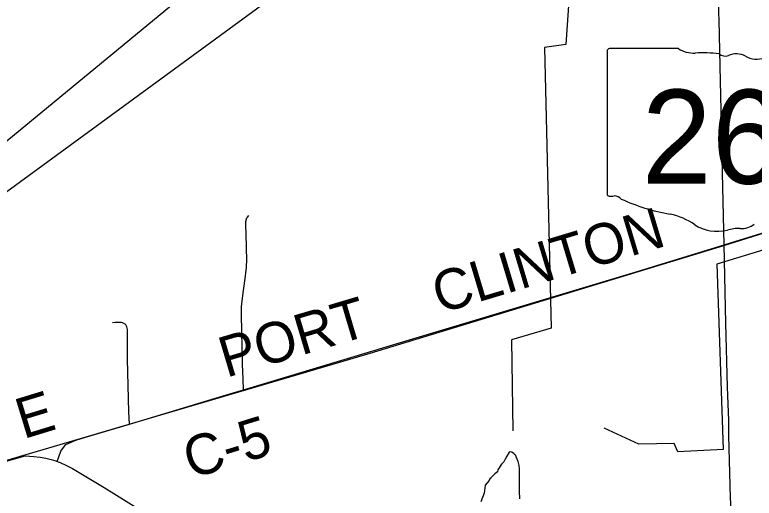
# Model space of a CAD drawing. Extents: x 0 to 34, y 0 to 22.
# Drawn here: x 6.003 to 6.521, y 18.17 to 18.509 of the extents above; entities that cross this region are included whole.
import ezdxf

# ---------------------------------------------------------------- set-up
doc = ezdxf.new("R2010")
doc.units = 0
for name, color, linetype in [('GM_X_County_Road', 7, 'Continuous'), ('GM_X_County_Road_Text', 7, 'Continuous'), ('GM_X_Minor_River', 7, 'Continuous'), ('GM_X_Rail_Line', 7, 'Continuous'), ('GM_X_State_Location', 7, 'Continuous'), ('GM_X_State_Route', 7, 'Continuous'), ('GM_X_State_Shield', 7, 'Continuous'), ('GM_X_Township_Road', 7, 'Continuous'), ('SH_Text', 7, 'Continuous')]:
    doc.layers.add(name, color=color, linetype=linetype)

msp = doc.modelspace()

# ---------------------------------------------------------------- linework, layer by layer
at = {"layer": 'GM_X_County_Road'}
msp.add_line((6.03864, 18.20727), (6.04563, 18.21028), dxfattribs=at)
for points in [[(6.4999, 18.34733), (6.50494, 18.34889), (6.53465, 18.35812), (6.66398, 18.39789), (6.6654, 18.39833)], [(6.16307, 18.2457), (6.26526, 18.27641), (6.43806, 18.32827), (6.4999, 18.34733)], [(6.08314, 18.22155), (6.11338, 18.23059), (6.15355, 18.24284), (6.16307, 18.2457)], [(6.04563, 18.21028), (6.05228, 18.21233), (6.08314, 18.22155)], [(6.0324, 18.19545), (6.03351, 18.19853), (6.03509, 18.2026), (6.03693, 18.2051), (6.03864, 18.20727)], [(5.93303, 18.17779), (5.93554, 18.17821), (5.93858, 18.1788), (5.94485, 18.18026), (5.95124, 18.18197), (5.96361, 18.18543), (5.99181, 18.19414), (6.00506, 18.19796), (6.01002, 18.19933)], [(6.01002, 18.19933), (6.01601, 18.19883), (6.02062, 18.1983), (6.02457, 18.19765), (6.02816, 18.19683), (6.03141, 18.19584), (6.0324, 18.19545), (6.03458, 18.19461), (6.03895, 18.19265), (6.04331, 18.19044)], [(6.04331, 18.19044), (6.04677, 18.18829), (6.06539, 18.17703), (6.2078, 18.08859), (6.26845, 18.05089), (6.29749, 18.0328)]]:
    msp.add_lwpolyline(points, dxfattribs=at)
at = {"layer": 'GM_X_Minor_River'}
for points in [[(6.39114, 18.52221), (6.38884, 18.4878), (6.37386, 18.48564), (6.37865, 18.28897), (6.35079, 18.28066), (6.35168, 18.21681)], [(6.97961, 18.48166), (6.49479, 18.33379), (6.49906, 18.20382), (6.46737, 18.20215), (6.46468, 18.20803), (6.44, 18.20753), (6.41565, 18.21882)], [(6.35656, 18.16909), (6.35645, 18.1746), (6.35635, 18.18087), (6.35642, 18.18581), (6.3563, 18.19018), (6.35614, 18.19246), (6.35543, 18.19532), (6.35415, 18.19875), (6.35378, 18.19971), (6.35284, 18.20029), (6.35266, 18.20086), (6.35097, 18.20183), (6.34965, 18.20204), (6.34908, 18.20186), (6.34752, 18.19904), (6.34635, 18.19696), (6.34557, 18.19564), (6.34537, 18.19508), (6.34383, 18.19358), (6.34131, 18.18963), (6.34091, 18.18811), (6.33918, 18.18662), (6.33668, 18.18438), (6.33649, 18.18381), (6.33553, 18.18325), (6.33513, 18.18212), (6.33243, 18.17874), (6.33159, 18.17325), (6.32942, 18.1672)]]:
    msp.add_lwpolyline(points, dxfattribs=at)
at = {"layer": 'GM_X_Rail_Line'}
msp.add_lwpolyline([(4.40206, 18.19809), (4.68917, 18.19409), (5.00635, 18.18976), (5.15875, 18.1876), (5.36248, 18.18265), (5.7183, 18.17956), (5.93191, 18.17708), (6.25187, 18.2714), (6.49949, 18.34686), (7.04327, 18.51787), (7.07913, 18.52777), (7.1289, 18.52993), (7.24173, 18.53643), (7.28965, 18.56333), (7.33819, 18.59766)], dxfattribs=at)
at = {"layer": 'GM_X_State_Route'}
for points in [[(6.4999, 18.34733), (6.4983, 18.4182), (6.49782, 18.44148), (6.49709, 18.47253), (6.4963, 18.50512), (6.4962, 18.50974), (6.49592, 18.5222), (6.49285, 18.64016), (6.4924, 18.65568), (6.49195, 18.67513), (6.49092, 18.71933), (6.48978, 18.75808), (6.48902, 18.78272), (6.48838, 18.8108), (6.48776, 18.84505), (6.48647, 18.88829), (6.48542, 18.93662), (6.48511, 18.95681), (6.48493, 18.96654), (6.48491, 18.98139)], [(6.5039, 18.18736), (6.5032, 18.21333), (6.503, 18.22418), (6.50208, 18.24745), (6.50093, 18.29243), (6.4999, 18.34733)], [(6.50646, 18.13067), (6.50637, 18.13629), (6.50621, 18.14474), (6.50599, 18.14914), (6.5058, 18.15195), (6.50564, 18.15363), (6.50542, 18.15546), (6.50478, 18.16187), (6.50436, 18.16989), (6.5039, 18.18736)]]:
    msp.add_lwpolyline(points, dxfattribs=at)
at = {"layer": 'GM_X_State_Shield'}
for p, q in [((6.41784, 18.48316), (6.41784, 18.3831)), ((6.46772, 18.48489), (6.41946, 18.48489))]:
    msp.add_line(p, q, dxfattribs=at)
for centre, major_axis, start_param, end_param in [((6.41973, 18.48338), (0.00191, 0), 1.712693, 3.28349), ((6.47922, 18.4965), (0.01852, 0), 4.042523, 4.731795), ((6.48536, 18.42871), (0.06648, 0), 1.404758, 1.657858), ((6.50829, 18.47233), (0.01111, 0), 0.950623, 2.079405), ((6.50045, 18.4839), (0.00534, 0), 3.836095, 5.185415), ((6.52262, 18.48819), (0.01336, 0), 4.081561, 5.145723), ((6.41974, 18.38289), (0.00193, 0), 3.00124, 4.508301), ((6.42004, 18.39312), (0.0147, 0), 4.665946, 4.897461), ((6.42304, 18.37733), (0.0053, 0), 0.519207, 1.627899), ((6.48996, 18.46723), (0.1262, 0), 4.195997, 4.488961), ((6.45233, 18.33815), (0.03949, 0), 0.823519, 1.323587), ((6.49504, 18.37683), (0.02506, 0), 4.026481, 4.996735), ((6.50952, 18.34224), (0.02059, 0), 1.495662, 1.94098), ((6.51135, 18.36934), (0.01335, 0), 4.691044, 5.507374)]:
    msp.add_ellipse(centre, major_axis=major_axis, ratio=0.8, start_param=start_param, end_param=end_param, dxfattribs=at)
at = {"layer": 'GM_X_Township_Road'}
for points in [[(6.16307, 18.2457), (6.16273, 18.25322), (6.16242, 18.26355), (6.16159, 18.29814), (6.16164, 18.30108), (6.16172, 18.30381), (6.16185, 18.30594), (6.16274, 18.31368), (6.16445, 18.32533), (6.16476, 18.32757), (6.16506, 18.33106), (6.16523, 18.33331), (6.16526, 18.33535), (6.16513, 18.34627), (6.16466, 18.36185), (6.16471, 18.36299), (6.16471, 18.36373), (6.1648, 18.36433), (6.16493, 18.36494), (6.16519, 18.36559), (6.16545, 18.36616), (6.16584, 18.36676), (6.16679, 18.36794)], [(6.08314, 18.22155), (6.08266, 18.23009), (6.08182, 18.26722), (6.08169, 18.28569), (6.08168, 18.28685), (6.08163, 18.28792), (6.08149, 18.28888), (6.08125, 18.28977), (6.08102, 18.29026), (6.08078, 18.29069), (6.08047, 18.2911), (6.08006, 18.29157), (6.07966, 18.29188), (6.07923, 18.2922), (6.07881, 18.29243), (6.07836, 18.2926), (6.07764, 18.29279), (6.07723, 18.29283), (6.0766, 18.29289), (6.07567, 18.29292), (6.0746, 18.29293), (6.07317, 18.29282), (6.07116, 18.29267)]]:
    msp.add_lwpolyline(points, dxfattribs=at)
at = {"layer": 'SH_Text'}
msp.add_lwpolyline([(5.61399, 18.10416), (9.32697, 20.82299), (9.32697, 21.16525)], close=True, dxfattribs=at)

# ---------------------------------------------------------------- texts
at = {"layer": 'GM_X_County_Road_Text'}
for s, height, rotation, p in [('CLINTON', 0.028409, 16.7127, (6.30052, 18.29892)), ('PORT', 0.028409, 16.5738, (6.15093, 18.25403)), ('E', 0.02841, 17.0212, (6.00877, 18.21097)), ('C-5', 0.028409, 17.1251, (6.12625, 18.18299))]:
    msp.add_text(s, height=height, rotation=rotation, dxfattribs=at).set_placement(p)
at = {"layer": 'GM_X_State_Location'}
for s in ['s', 'r']:
    msp.add_text(s, height=0.0000947, dxfattribs=at).set_placement((6.49838, 18.42648))
msp.add_text('269', height=0.0000947, rotation=0, dxfattribs=at).set_placement((6.46495, 18.41959))
at = {"layer": 'GM_X_State_Shield'}
msp.add_text('269', height=0.065918, dxfattribs=at).set_placement((6.44208, 18.39016))

doc.saveas('drawing.dxf')
